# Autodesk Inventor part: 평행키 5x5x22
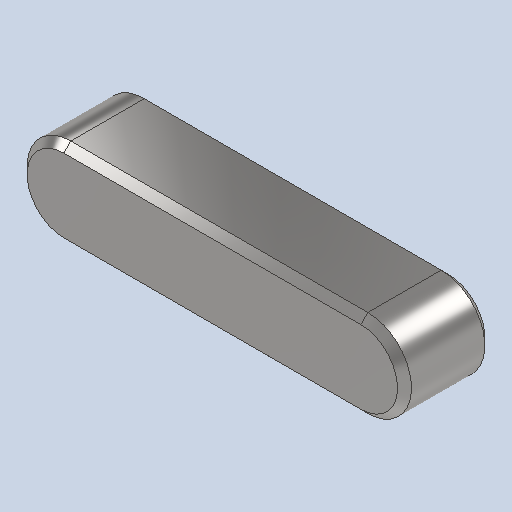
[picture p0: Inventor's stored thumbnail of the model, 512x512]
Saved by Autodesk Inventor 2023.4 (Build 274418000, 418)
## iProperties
Created: 2024-09
Part Number: 평행키 5x5x22
Material: 강철, 연강
Description: 키 및 해당 키홈
Document SubType Name: Modeling
Designer: 11
Density: 7.85 g/cm^3
Appearance: 기본값
Author: jhkim
Sending System: Autodesk Inventor 2025
Preprocessor: ST-DEVELOPER v20
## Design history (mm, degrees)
node "평행키 5x5x221"
node "솔리드1"
body "Solid1"
